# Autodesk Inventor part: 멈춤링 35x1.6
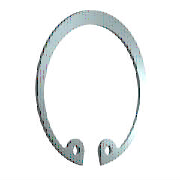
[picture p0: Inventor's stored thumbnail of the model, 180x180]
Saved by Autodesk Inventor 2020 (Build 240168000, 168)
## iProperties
Created: 2012-02
Part Number: 멈춤링 35x1.6
Material: 강철, 연강
Description: 리테이닝 링(C형)
Document SubType Name: Modeling
Standard: KS B 1336
Designer: mduedu
Standards Organization: KS
Language: ko-KR
Size Designation: 35x1.6
Categories: <MemberInstance><Categories><Category DisplayName="샤프트 부품" InternalName="7f7aeb1f-a693-4053-b835-cee3144e0d98" Mnemonic="SHFT"><Category DisplayName="써클립" Inter
Density: 1 g/cm^3
Appearance: 파란색 - 벽 페인트 - 광택
IsCustomPart: 1
Author: mduedu
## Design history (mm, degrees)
sketch "스케치1"
  geometry: L1 (0, 15.113)-(0, -73.177) reference; L2 (-45.5, 0)-(45.5, 0) reference; L3 (-4.964, 1)-(1.502, 1); L4 (0, -2.5)-(-5.307, -2.5); L5 (0, -17.5)-(-8.583, -33.888); L6 (-8.583, -33.888)-(-21.772, -26.981); L7 (-7.377, -31.585)-(-17.631, -26.214); L8 (-5.162, -32.745)-(-6.29, -34.898); L9 (5.162, -32.745)-(6.29, -34.898); C1 r 1.25 at (-7.377, -31.585); C2 r 1.25 at (7.377, -31.585); A1 r 15.875 centre (0, -18.375) between (11.82, -28.972) and (-11.82, -28.972); A2 r 18.5 centre (0, -17.5) between (6.29, -34.898) and (-6.29, -34.898); A3 r 2.5 centre (-7.377, -31.585) between (-5.162, -32.745) and (-8.668, -29.444); A4 r 2.5 centre (-9.959, -27.303) between (-11.82, -28.972) and (-8.668, -29.444); A5 r 2.5 centre (9.959, -27.303) between (8.668, -29.444) and (11.82, -28.972); A6 r 2.5 centre (7.377, -31.585) between (8.668, -29.444) and (5.162, -32.745); 3 further points
  constraints: 15 point on circle, 14 end point, 9 symmetric about line, 8 centre point, 6 tangent, 4 coincident, 4 point on line, 3 perpendicular, 1 parallel, 4 other
  dimensions: "d8" = 0.875 distance of A1.centre L5.start (= 0.25 x SRB1); "d38" = 3.5 distance between parallel lines of L4 L3 (= SRB1); "d39" = 17.5 distance from line of L5.start L2 (= 0.5 x WD); "d43" = 18.5 radius of A2 (= 0.5 x ND); "d45" = 2.6 distance between parallel lines of L7 L6 (= 0.5 x SRB2); "d46" = 2.5 radius of A4 (= SD5); "d47" = 6.29 distance from line of L1 L8.end (= 0.17 x ND); "d48" = 2.5 diameter of C1 (= SD5); "d49" = 2.5 radius of A3 (= SD5)
extrude "본체" new body sketch "스케치1" distance "d2" = 1.6 (= SD); taper "d3" = 0 deg
workaxis "Work Axis1"
workaxis "Work Axis2"
workplane "Work Plane1"
body "Solid1"
other parameters: "WD" = 35 [user parameter; used in 3 equation terms], "SD" = 1.6 [user parameter; used in 1 equation term], "SRB1" = 3.5 [user parameter; used in 2 equation terms], "ND" = 37 [user parameter; used in 2 equation terms], "SRB2" = 5.2 [user parameter; used in 1 equation term], "SD5" = 2.5 [user parameter; used in 3 equation terms], "d50" = 0, "d51" = 0, "d52" = 0, "d53" = 0, "WDMIN" = 34 [user parameter], "SD6" = 37.8 [user parameter], "WDMAX" = 35 (= WD) [user parameter], "NND" = 35 (= WD) [user parameter]
